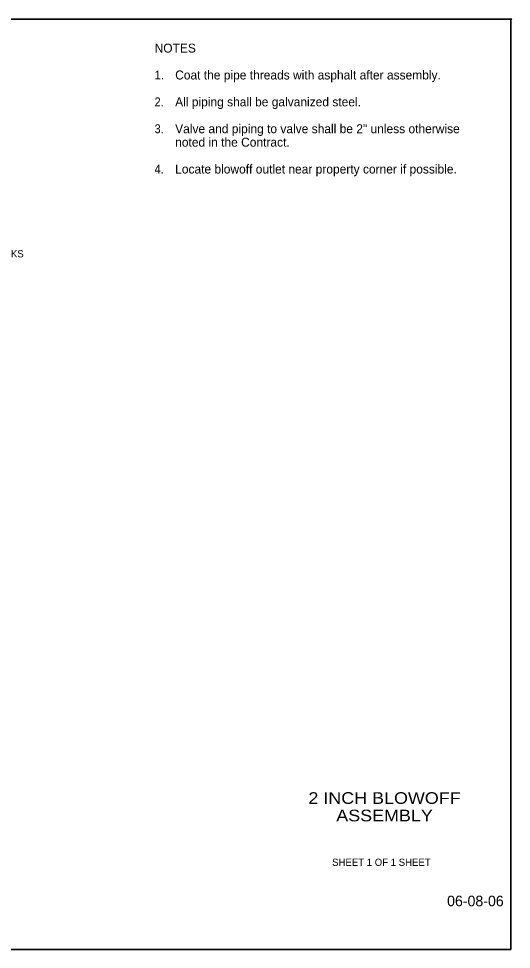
# Model space of a CAD drawing. Extents: x 99860 to 103153, y 99998 to 102077.
# Drawn here: x 102052 to 103153, y 100000 to 102077 of the extents above; entities that cross this region are included whole.
import ezdxf
from ezdxf.enums import TextEntityAlignment as Align

# ---------------------------------------------------------------- set-up
doc = ezdxf.new("R2010")
doc.units = 0
doc.header["$LTSCALE"] = 6.4
doc.header["$PDMODE"] = 32
doc.header["$PDSIZE"] = 3.2
for name, color, linetype, lineweight in [('1', 7, 'Continuous', 13), ('11', 7, 'Continuous', 13), ('20', 7, 'Continuous', 13)]:
    doc.layers.add(name, color=color, linetype=linetype, lineweight=lineweight)
for name, color, linetype in [('27', 7, 'Continuous'), ('60', 7, 'Continuous'), ('62', 7, 'Continuous')]:
    doc.layers.add(name, color=color, linetype=linetype)

msp = doc.modelspace()

# ---------------------------------------------------------------- linework, layer by layer
at = {"layer": '1', "lineweight": 35}
msp.add_lwpolyline([(99862, 99999.5), (103151, 99999.5), (103151, 102075.5), (99862, 102075.5)], close=True, dxfattribs=at)
at = {"layer": '60'}
msp.add_point((103151, 102075.5), dxfattribs=at)

# ---------------------------------------------------------------- texts
at = {"layer": '11'}
msp.add_text('06-08-06', height=23.62, dxfattribs=at).set_placement((103072.262, 100095.777), align=Align.CENTER)
at = {"layer": '20'}
for s, height, p in [('NOTES', 20, (102356.006, 102001.261)), ('TWO CONCRETE BLOCKS', 16, (101795.038, 101544.259))]:
    msp.add_text(s, height=height, dxfattribs=at).set_placement(p)
for s, width, p in [('1.', 0.95, (102356.006, 101941.261)), ('2.', 0.9, (102356.006, 101881.261)), ('3.', 0.9, (102356.006, 101821.261)), ('4.', 0.9, (102356.006, 101731.261))]:
    msp.add_text(s, height=20, dxfattribs=dict(at, width=width)).set_placement(p)
at = {"layer": '27'}
for s, p in [('Coat the pipe threads with asphalt after assembly.', (102401.916, 101941.261)), ('All piping shall be galvanized steel.', (102401.916, 101881.261)), ('Valve and piping to valve shall be 2" unless otherwise', (102401.916, 101821.261)), ('noted in the Contract.', (102401.916, 101791.261)), ('Locate blowoff outlet near property corner if possible.', (102401.916, 101731.261))]:
    msp.add_text(s, height=20, dxfattribs=at).set_placement(p)
at = {"layer": '62', "width": 1.15}
for s, p in [('2 INCH BLOWOFF', (102869.356, 100324.3)), ('ASSEMBLY', (102869.356, 100285.3))]:
    msp.add_text(s, height=26, dxfattribs=at).set_placement(p, align=Align.CENTER)
at = {"layer": '62'}
msp.add_text('SHEET 1 OF 1 SHEET', height=16, dxfattribs=at).set_placement((102862.358, 100185.938), align=Align.CENTER)

doc.saveas('drawing.dxf')
